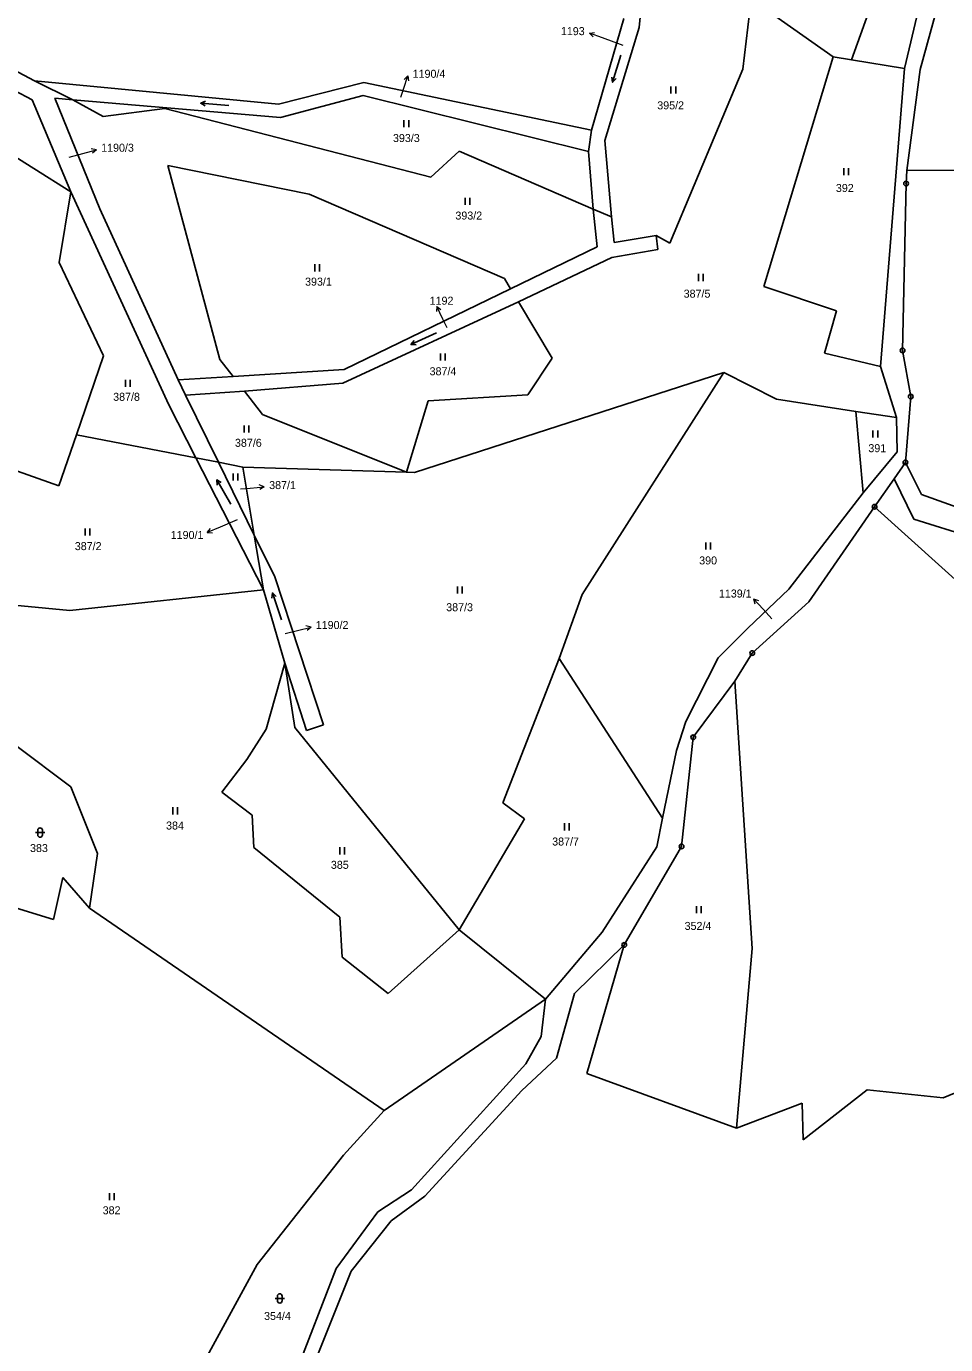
# Model space of a CAD drawing. Extents: x -765428 to -762163, y -1107632 to -1104975.
# Drawn here: x -764252.2 to -764056.9, y -1106880.1 to -1106600.1 of the extents above; entities that cross this region are included whole.
import ezdxf
from ezdxf.enums import TextEntityAlignment as Align

# ---------------------------------------------------------------- set-up
doc = ezdxf.new("R2010")
doc.units = 0
doc.header["$LTSCALE"] = 0.68
for name, color, linetype, lineweight in [('1', 7, 'Continuous', 25), ('3', 7, 'Continuous', 25), ('7', 7, 'Continuous', 13), ('8', 7, 'Continuous', 25)]:
    doc.layers.add(name, color=color, linetype=linetype, lineweight=lineweight)
doc.layers.add('2', color=7, linetype='Continuous')

msp = doc.modelspace()

# ---------------------------------------------------------------- linework, layer by layer
at = {"layer": '1'}
for p, q in [((-764053.62, -1106577.6), (-764062.34, -1106609.21)), ((-764251.03, -1106615.67), (-764316.87, -1106580.85)), ((-764122.07, -1106600.28), (-764120.1, -1106580.06)), ((-764068, -1106582.41), (-764076.95, -1106607.17)), ((-764059.71, -1106583.99), (-764065.69, -1106609.05)), ((-764250.5, -1106611.63), (-764292.59, -1106589.42)), ((-764098.26, -1106594.25), (-764100.05, -1106609.19)), ((-764080.83, -1106606.52), (-764098.26, -1106594.25)), ((-764132.16, -1106622.12), (-764125.34, -1106598.43)), ((-764129.35, -1106624.3), (-764122.07, -1106600.28)), ((-764292.69, -1106603.84), (-764242.78, -1106635.19)), ((-764095.6, -1106655.32), (-764080.83, -1106606.52)), ((-764076.95, -1106607.17), (-764080.83, -1106606.52)), ((-764065.69, -1106609.05), (-764076.95, -1106607.17)), ((-764100.05, -1106609.19), (-764115.54, -1106646.16)), ((-764065.69, -1106609.05), (-764070.78, -1106672.31)), ((-764062.34, -1106609.21), (-764065.16, -1106630.68)), ((-764242.36, -1106615.66), (-764250.5, -1106611.63)), ((-764198.68, -1106616.63), (-764250.5, -1106611.63)), ((-764180.54, -1106612.02), (-764198.68, -1106616.63)), ((-764132.16, -1106622.12), (-764180.54, -1106612.02)), ((-764242.78, -1106635.19), (-764251.03, -1106615.67)), ((-764236.64, -1106638.86), (-764246.21, -1106615.33)), ((-764242.36, -1106615.66), (-764246.21, -1106615.33)), ((-764235.95, -1106619.23), (-764242.36, -1106615.66)), ((-764242.36, -1106615.66), (-764198.26, -1106619.4)), ((-764180.7, -1106614.76), (-764198.26, -1106619.4)), ((-764132.82, -1106626.63), (-764180.7, -1106614.76)), ((-764222.84, -1106617.49), (-764235.95, -1106619.23)), ((-764166.3, -1106632.09), (-764222.84, -1106617.49)), ((-764132.82, -1106626.63), (-764132.16, -1106622.12)), ((-764127.96, -1106640.57), (-764129.35, -1106624.3)), ((-764160.28, -1106626.59), (-764166.3, -1106632.09)), ((-764131.81, -1106638.89), (-764160.28, -1106626.59)), ((-764131.81, -1106638.89), (-764132.82, -1106626.63)), ((-764222.17, -1106629.6), (-764211.11, -1106670.82)), ((-764192.18, -1106635.75), (-764222.17, -1106629.6)), ((-764065.36, -1106633.47), (-764065.16, -1106630.68)), ((-764065.16, -1106630.68), (-764036.77, -1106630.61)), ((-764245.26, -1106650.25), (-764242.78, -1106635.19)), ((-764242.78, -1106635.19), (-764222, -1106680.49)), ((-764150.66, -1106653.65), (-764192.18, -1106635.75)), ((-764066.08, -1106668.92), (-764065.36, -1106633.47)), ((-764219.96, -1106675.14), (-764236.64, -1106638.86)), ((-764130.98, -1106646.88), (-764131.81, -1106638.89)), ((-764127.96, -1106640.57), (-764131.81, -1106638.89)), ((-764127.33, -1106645.96), (-764127.96, -1106640.57)), ((-764149.36, -1106655.81), (-764130.98, -1106646.88)), ((-764118.46, -1106644.51), (-764127.33, -1106645.96)), ((-764118.46, -1106644.51), (-764115.54, -1106646.16)), ((-764118.08, -1106647.51), (-764118.46, -1106644.51)), ((-764127.86, -1106649.18), (-764147.71, -1106658.56)), ((-764127.86, -1106649.18), (-764118.08, -1106647.51)), ((-764235.85, -1106670.1), (-764245.26, -1106650.25)), ((-764149.36, -1106655.81), (-764150.66, -1106653.65)), ((-764080.13, -1106660.5), (-764095.6, -1106655.32)), ((-764184.74, -1106673), (-764149.36, -1106655.81)), ((-764147.71, -1106658.56), (-764184.98, -1106675.9)), ((-764140.51, -1106670.57), (-764147.71, -1106658.56)), ((-764082.65, -1106669.48), (-764080.13, -1106660.5)), ((-764064.35, -1106678.73), (-764066.08, -1106668.92)), ((-764241.61, -1106686.83), (-764235.85, -1106670.1)), ((-764208.32, -1106674.43), (-764211.11, -1106670.82)), ((-764145.68, -1106678.38), (-764140.51, -1106670.57)), ((-764070.78, -1106672.31), (-764082.65, -1106669.48)), ((-764219.96, -1106675.14), (-764208.32, -1106674.43)), ((-764208.32, -1106674.43), (-764184.74, -1106673)), ((-764169.8, -1106694.83), (-764104.05, -1106673.62)), ((-764104.05, -1106673.62), (-764134.19, -1106720.76)), ((-764092.88, -1106679.26), (-764104.05, -1106673.62)), ((-764067.37, -1106683.14), (-764070.78, -1106672.31)), ((-764218.46, -1106678.4), (-764219.96, -1106675.14)), ((-764218.46, -1106678.4), (-764205.9, -1106677.56)), ((-764205.9, -1106677.56), (-764184.98, -1106675.9)), ((-764202.07, -1106682.51), (-764205.9, -1106677.56)), ((-764222, -1106680.49), (-764216.22, -1106691.76)), ((-764211.42, -1106692.69), (-764218.46, -1106678.4)), ((-764171.51, -1106694.78), (-764166.91, -1106679.61)), ((-764166.91, -1106679.61), (-764145.68, -1106678.38)), ((-764076.02, -1106681.87), (-764092.88, -1106679.26)), ((-764065.49, -1106692.7), (-764064.35, -1106678.73)), ((-764202.07, -1106682.51), (-764171.51, -1106694.78)), ((-764076.02, -1106681.87), (-764067.37, -1106683.14)), ((-764076.02, -1106681.87), (-764074.48, -1106699.14)), ((-764067.37, -1106683.14), (-764067.21, -1106690.48)), ((-764278.35, -1106685.97), (-764245.35, -1106697.7)), ((-764245.35, -1106697.7), (-764241.61, -1106686.83)), ((-764216.22, -1106691.76), (-764241.61, -1106686.83)), ((-764211.42, -1106692.69), (-764216.22, -1106691.76)), ((-764216.22, -1106691.76), (-764201.84, -1106719.8)), ((-764067.21, -1106690.48), (-764074.48, -1106699.14)), ((-764206.26, -1106693.69), (-764211.42, -1106692.69)), ((-764203.81, -1106708.15), (-764211.42, -1106692.69)), ((-764206.26, -1106693.69), (-764203.81, -1106708.15)), ((-764206.26, -1106693.69), (-764171.51, -1106694.78)), ((-764067.88, -1106696.18), (-764065.49, -1106692.7)), ((-764065.49, -1106692.7), (-764062.06, -1106699.52)), ((-764171.51, -1106694.78), (-764169.8, -1106694.83)), ((-764067.88, -1106696.18), (-764072.04, -1106702.13)), ((-764067.88, -1106696.18), (-764063.68, -1106704.76)), ((-764074.48, -1106699.14), (-764090.25, -1106719.67)), ((-764062.06, -1106699.52), (-764009.24, -1106718.56)), ((-764072.04, -1106702.13), (-764085.98, -1106722.32)), ((-763956.29, -1106806.86), (-764072.04, -1106702.13)), ((-764063.68, -1106704.76), (-764051.43, -1106708.61)), ((-764199.44, -1106717.03), (-764203.81, -1106708.15)), ((-764203.81, -1106708.15), (-764201.84, -1106719.8)), ((-764201.84, -1106719.8), (-764242.99, -1106724.15)), ((-764197.33, -1106735.35), (-764201.84, -1106719.8)), ((-764189.11, -1106748.48), (-764199.44, -1106717.03)), ((-764090.25, -1106719.67), (-764098.99, -1106727.95)), ((-764242.99, -1106724.15), (-764277.34, -1106720.91)), ((-764134.19, -1106720.76), (-764139.02, -1106734.39)), ((-764085.98, -1106722.32), (-764098.02, -1106733.21)), ((-764098.99, -1106727.95), (-764105.27, -1106734.22)), ((-764101.73, -1106739.22), (-764098.02, -1106733.21)), ((-764201.32, -1106749.38), (-764197.33, -1106735.35)), ((-764195.24, -1106749.04), (-764197.33, -1106735.35)), ((-764197.33, -1106735.35), (-764192.7, -1106749.66)), ((-764151.02, -1106765.04), (-764139.02, -1106734.39)), ((-764139.02, -1106734.39), (-764117.13, -1106768.28)), ((-764112.15, -1106747.78), (-764105.27, -1106734.22)), ((-764101.73, -1106739.22), (-764110.55, -1106751.1)), ((-764098.06, -1106795.98), (-764101.73, -1106739.22)), ((-764114.09, -1106753.94), (-764112.15, -1106747.78)), ((-764205.41, -1106755.82), (-764201.32, -1106749.38)), ((-764160.29, -1106792), (-764195.24, -1106749.04)), ((-764192.7, -1106749.66), (-764189.11, -1106748.48)), ((-764242.8, -1106761.67), (-764254.49, -1106752.86)), ((-764113.04, -1106774.31), (-764110.55, -1106751.1)), ((-764210.68, -1106762.79), (-764205.41, -1106755.82)), ((-764117.13, -1106768.28), (-764114.09, -1106753.94)), ((-764237.14, -1106775.81), (-764242.8, -1106761.67)), ((-764204.3, -1106767.63), (-764210.68, -1106762.79)), ((-764146.4, -1106768.42), (-764151.02, -1106765.04)), ((-764203.92, -1106774.49), (-764204.3, -1106767.63)), ((-764146.4, -1106768.42), (-764160.29, -1106792)), ((-764117.13, -1106768.28), (-764118.31, -1106774.41)), ((-764185.63, -1106789.31), (-764203.92, -1106774.49)), ((-764118.31, -1106774.41), (-764129.88, -1106792.48)), ((-764113.04, -1106774.31), (-764125.21, -1106795.23)), ((-764246.51, -1106789.83), (-764244.46, -1106780.9)), ((-764244.46, -1106780.9), (-764238.86, -1106787.39)), ((-764258.31, -1106786.23), (-764246.51, -1106789.83)), ((-764185.13, -1106797.8), (-764185.63, -1106789.31)), ((-764160.29, -1106792), (-764175.38, -1106805.56)), ((-764141.95, -1106806.76), (-764160.29, -1106792)), ((-764129.88, -1106792.48), (-764141.95, -1106806.76)), ((-764135.82, -1106805.53), (-764125.21, -1106795.23)), ((-764133.18, -1106822.51), (-764125.21, -1106795.23)), ((-764175.38, -1106805.56), (-764185.13, -1106797.8)), ((-764098.06, -1106795.98), (-764101.35, -1106834.17)), ((-764139.59, -1106819.31), (-764135.82, -1106805.53)), ((-764141.95, -1106806.76), (-764176.22, -1106830.4)), ((-764142.87, -1106814.67), (-764141.95, -1106806.76)), ((-764146.15, -1106820.51), (-764142.87, -1106814.67)), ((-764170.41, -1106847.26), (-764146.15, -1106820.51)), ((-764146.95, -1106826.12), (-764139.59, -1106819.31)), ((-764101.35, -1106834.17), (-764133.18, -1106822.51)), ((-764040.99, -1106820.96), (-764057.46, -1106827.68)), ((-764167.61, -1106848.62), (-764146.95, -1106826.12)), ((-764073.61, -1106826.03), (-764087.19, -1106836.61)), ((-764057.46, -1106827.68), (-764073.61, -1106826.03)), ((-764087.39, -1106828.87), (-764101.35, -1106834.17)), ((-764087.19, -1106836.61), (-764087.39, -1106828.87)), ((-764176.22, -1106830.4), (-764184.87, -1106839.89)), ((-764184.87, -1106839.89), (-764203.18, -1106863.09)), ((-764177.54, -1106851.9), (-764170.41, -1106847.26)), ((-764174.74, -1106853.82), (-764167.61, -1106848.62)), ((-764186.42, -1106863.98), (-764177.54, -1106851.9)), ((-764183.21, -1106864.52), (-764174.74, -1106853.82)), ((-764203.18, -1106863.09), (-764221.14, -1106896.01)), ((-764199.42, -1106897.54), (-764186.42, -1106863.98)), ((-764196.71, -1106898.18), (-764183.21, -1106864.52))]:
    msp.add_line(p, q, dxfattribs=at)
msp.add_lwpolyline([(-764176.22, -1106830.4), (-764238.86, -1106787.39), (-764237.14, -1106775.81)], dxfattribs=at)
at = {"layer": '3'}
for p, q in [((-764127.7, -1106611.943), (-764127.894, -1106610.862)), ((-764115.291, -1106614.33), (-764115.291, -1106612.83)), ((-764114.29, -1106614.33), (-764114.29, -1106612.83)), ((-764215.175, -1106616.389), (-764214.158, -1106615.974)), ((-764172.021, -1106621.52), (-764172.021, -1106620.02)), ((-764171.02, -1106621.52), (-764171.02, -1106620.02)), ((-764078.561, -1106631.67), (-764078.561, -1106630.17)), ((-764077.56, -1106631.67), (-764077.56, -1106630.17)), ((-764159.041, -1106637.99), (-764159.041, -1106636.49)), ((-764158.04, -1106637.99), (-764158.04, -1106636.49)), ((-764190.981, -1106652.12), (-764190.981, -1106650.62)), ((-764189.98, -1106652.12), (-764189.98, -1106650.62)), ((-764109.431, -1106654.18), (-764109.431, -1106652.68)), ((-764108.43, -1106654.18), (-764108.43, -1106652.68)), ((-764170.56, -1106667.649), (-764169.871, -1106666.794)), ((-764164.241, -1106671.07), (-764164.241, -1106669.57)), ((-764163.24, -1106671.07), (-764163.24, -1106669.57)), ((-764231.171, -1106676.68), (-764231.171, -1106675.18)), ((-764230.17, -1106676.68), (-764230.17, -1106675.18)), ((-764205.951, -1106686.37), (-764205.951, -1106684.87)), ((-764204.95, -1106686.37), (-764204.95, -1106684.87)), ((-764072.381, -1106687.41), (-764072.381, -1106685.91)), ((-764071.38, -1106687.41), (-764071.38, -1106685.91)), ((-764211.791, -1106696.413), (-764210.868, -1106697.008)), ((-764208.341, -1106696.58), (-764208.341, -1106695.08)), ((-764207.34, -1106696.58), (-764207.34, -1106695.08)), ((-764239.771, -1106708.23), (-764239.771, -1106706.73)), ((-764238.77, -1106708.23), (-764238.77, -1106706.73)), ((-764107.921, -1106711.23), (-764107.921, -1106709.73)), ((-764106.92, -1106711.23), (-764106.92, -1106709.73)), ((-764160.681, -1106720.57), (-764160.681, -1106719.07)), ((-764159.68, -1106720.57), (-764159.68, -1106719.07)), ((-764199.964, -1106720.454), (-764199.172, -1106721.215)), ((-764221.101, -1106767.49), (-764221.101, -1106765.99)), ((-764220.1, -1106767.49), (-764220.1, -1106765.99)), ((-764137.911, -1106770.88), (-764137.911, -1106769.38)), ((-764136.91, -1106770.88), (-764136.91, -1106769.38)), ((-764250.331, -1106771.351), (-764248.329, -1106771.351)), ((-764249.831, -1106770.851), (-764249.831, -1106771.852)), ((-764248.829, -1106771.852), (-764248.829, -1106770.851)), ((-764185.631, -1106775.98), (-764185.631, -1106774.48)), ((-764184.63, -1106775.98), (-764184.63, -1106774.48)), ((-764109.891, -1106788.48), (-764109.891, -1106786.98)), ((-764108.89, -1106788.48), (-764108.89, -1106786.98)), ((-764234.591, -1106849.47), (-764234.591, -1106847.97)), ((-764233.59, -1106849.47), (-764233.59, -1106847.97)), ((-764199.401, -1106870.321), (-764197.399, -1106870.321)), ((-764198.901, -1106869.821), (-764198.901, -1106870.822)), ((-764197.899, -1106870.822), (-764197.899, -1106869.821))]:
    msp.add_line(p, q, dxfattribs=at)
for points in [[(-764125.946, -1106606.205), (-764127.7, -1106611.943), (-764126.935, -1106611.155)], [(-764209.198, -1106616.911), (-764215.175, -1106616.389), (-764214.245, -1106616.973)], [(-764165.079, -1106665.209), (-764170.56, -1106667.649), (-764169.463, -1106667.71)], [(-764208.791, -1106701.609), (-764211.791, -1106696.413), (-764211.737, -1106697.51)], [(-764198.011, -1106726.128), (-764199.964, -1106720.454), (-764200.12, -1106721.542)]]:
    msp.add_lwpolyline(points, dxfattribs=at)
for centre, start, end in [((-764249.33, -1106770.8509), 0, 180), ((-764249.33, -1106771.8509), 180, 359.98789), ((-764198.4, -1106869.8209), 0, 180), ((-764198.4, -1106870.8209), 180, 359.98789)]:
    msp.add_arc(centre, 0.5, start, end, dxfattribs=at)
at = {"layer": '7'}
for p, q in [((-764132.63, -1106601.514), (-764131.86, -1106602.327)), ((-764171.193, -1106610.566), (-764171.978, -1106611.364)), ((-764237.341, -1106626.293), (-764238.438, -1106626.069)), ((-764165.066, -1106659.563), (-764165.077, -1106660.682)), ((-764201.72, -1106697.898), (-764202.762, -1106697.487)), ((-764213.812, -1106707.633), (-764212.695, -1106707.702)), ((-764097.748, -1106721.66), (-764097.45, -1106722.739)), ((-764191.758, -1106727.694), (-764192.851, -1106727.45))]:
    msp.add_line(p, q, dxfattribs=at)
for points in [[(-764125.47, -1106604.13), (-764129.81, -1106602.54), (-764132.63, -1106601.514), (-764131.518, -1106601.386)], [(-764172.66, -1106615.08), (-764172.12, -1106613.42), (-764171.193, -1106610.566), (-764171.026, -1106611.673)], [(-764243.15, -1106627.87), (-764240.24, -1106627.07), (-764237.341, -1106626.293), (-764238.179, -1106627.036)], [(-764162.85, -1106664.14), (-764163.75, -1106662.26), (-764165.066, -1106659.563), (-764164.176, -1106660.243)], [(-764206.75, -1106698.33), (-764204.71, -1106698.16), (-764201.72, -1106697.898), (-764202.674, -1106698.485)], [(-764207.47, -1106704.92), (-764211.05, -1106706.46), (-764213.812, -1106707.633), (-764213.086, -1106706.78)], [(-764093.9, -1106725.97), (-764095.74, -1106723.89), (-764097.748, -1106721.66), (-764096.706, -1106722.069)], [(-764197.24, -1106729.08), (-764194.67, -1106728.42), (-764191.758, -1106727.694), (-764192.609, -1106728.422)]]:
    msp.add_lwpolyline(points, dxfattribs=at)
at = {"layer": '8'}
for centre, radius in [((-764065.36, -1106633.4699), 0.5), ((-764065.36, -1106633.4699), 0.0303), ((-764066.08, -1106668.9199), 0.5), ((-764066.08, -1106668.9199), 0.0303), ((-764064.35, -1106678.7299), 0.5), ((-764064.35, -1106678.7299), 0.0303), ((-764065.49, -1106692.6999), 0.5), ((-764065.49, -1106692.6999), 0.0303), ((-764072.04, -1106702.1299), 0.5), ((-764072.04, -1106702.1299), 0.0303), ((-764098.02, -1106733.2099), 0.5), ((-764098.02, -1106733.2099), 0.0303), ((-764110.55, -1106751.0999), 0.5), ((-764110.55, -1106751.0999), 0.0303), ((-764113.04, -1106774.3099), 0.5), ((-764113.04, -1106774.3099), 0.0303), ((-764125.21, -1106795.2299), 0.5), ((-764125.21, -1106795.2299), 0.0303)]:
    msp.add_circle(centre, radius, dxfattribs=at)

# ---------------------------------------------------------------- texts
at = {"layer": '2'}
for s, p in [('1193', (-764133.63, -1106601.935)), ('1192', (-764161.51, -1106659.205)), ('1190/1', (-764214.619, -1106708.975)), ('1139/1', (-764098.159, -1106721.415))]:
    msp.add_text(s, height=1.7, dxfattribs=at).set_placement(p, align=Align.RIGHT)
for s, p in [('1190/4', (-764170.18, -1106610.995)), ('395/2', (-764118.21, -1106617.695)), ('1190/3', (-764236.35, -1106626.705)), ('392', (-764080.26, -1106635.255)), ('391', (-764073.36, -1106690.535)), ('387/1', (-764200.66, -1106698.375)), ('390', (-764109.3, -1106714.385)), ('1190/2', (-764190.76, -1106728.105)), ('384', (-764222.56, -1106770.705)), ('383', (-764251.46, -1106775.495)), ('352/4', (-764112.4, -1106792.035)), ('382', (-764236.03, -1106852.455)), ('354/4', (-764201.74, -1106874.905))]:
    msp.add_text(s, height=1.7, dxfattribs=at).set_placement(p)
for s, p in [('393/3', (-764171.51, -1106624.645)), ('393/2', (-764158.25, -1106641.115)), ('393/1', (-764190.19, -1106655.155)), ('387/5', (-764109.76, -1106657.705)), ('387/4', (-764163.73, -1106674.195)), ('387/8', (-764230.96, -1106679.625)), ('387/6', (-764205.08, -1106689.395)), ('387/2', (-764239.11, -1106711.345)), ('387/3', (-764160.2, -1106724.325)), ('387/7', (-764137.69, -1106774.105)), ('385', (-764185.649, -1106779.055))]:
    msp.add_text(s, height=1.7, dxfattribs=at).set_placement(p, align=Align.CENTER)

doc.saveas('drawing.dxf')
